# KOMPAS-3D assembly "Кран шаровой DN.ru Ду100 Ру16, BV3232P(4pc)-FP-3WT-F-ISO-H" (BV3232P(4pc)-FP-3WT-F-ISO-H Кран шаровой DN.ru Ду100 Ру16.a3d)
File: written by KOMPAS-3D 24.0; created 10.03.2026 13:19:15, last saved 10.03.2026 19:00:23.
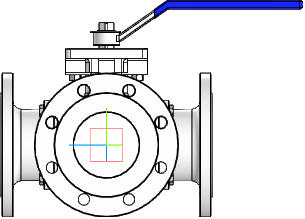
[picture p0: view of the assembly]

Document properties: Автор: R2D2; Полное имя файла: E:\Работа\Зайцев\BV3232P(4pc)-FP-3WT-F-ISO-H Кран шаровой DN.ru Ду15-100 Ру16\DN100\исходные материалы\BV3232P(4pc)-FP-3WT-F-ISO-H Кран шаровой DN.ru Ду100 Ру16.a3d

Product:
- Component [assembly]: Сборка1  | qty 1  | pos. 1  | Масса: 49.435377; Автор: R2D2; source file: dn100_3d_step.a3d
- Part/product: Кран шаровой DN.ru Ду100 Ру16  | designation BV3232P(4pc)-FP-3WT-F-ISO-H
    Масса: 58.5
    Раздел спецификации: Прочие изделия
    Примечание: D160-36354

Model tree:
1. Эскиз:1  (labels: Грань.Твердое тело1; Ребро.Твердое тело1)
2. Элемент выдавливания:1  (labels: Грань.Твердое тело1; Твердое тело1)
     Расстояние 2 = 0.01

Referenced files in E:\Работа\Зайцев\BV3232P(4pc)-FP-3WT-F-ISO-H Кран шаровой DN.ru Ду15-100 Ру16\DN100\исходные материалы\: dn100_3d_step.a3d
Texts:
  BV3232P(4pc)-FP-3WT-F-ISO-H
  Сборка1 Сборка1
  Ось Z.Начало координат
  Ось Y.Начало координат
